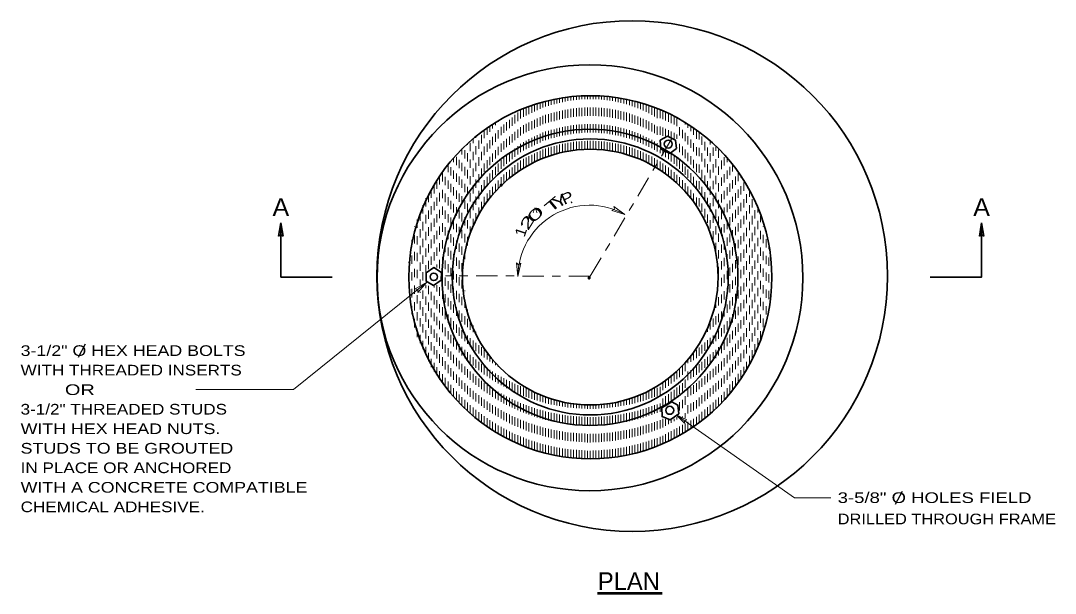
# Model space of a CAD drawing. Extents: x 21 to 35.7, y -17 to 3.5.
# Drawn here: x 20.95 to 33.31, y -3.3 to 3.53 of the extents above; entities that cross this region are included whole.
import ezdxf
from ezdxf.enums import TextEntityAlignment as Align

# ---------------------------------------------------------------- set-up
doc = ezdxf.new("R2010")
doc.units = 0
doc.header["$LTSCALE"] = 0.051
doc.header["$PDMODE"] = 32
doc.header["$PDSIZE"] = 0.0255
doc.linetypes.add('DOT_DASHED', pattern=[7.7, 5, -1.2, 0.3, -1.2])
doc.linetypes.add('DOTTED', pattern=[1.5, 0.3, -1.2])
for name, color, linetype, lineweight in [('1', 7, 'Continuous', 35), ('10', 7, 'Continuous', 13), ('12', 7, 'Continuous', 53), ('6', 7, 'DOTTED', 13)]:
    doc.layers.add(name, color=color, linetype=linetype, lineweight=lineweight)
doc.layers.add('13', color=7, linetype='Continuous')

msp = doc.modelspace()

# ---------------------------------------------------------------- linework, layer by layer
at = {"layer": '1'}
for points in [[(28.59758, 2.00233), (28.59133, 2.10583), (28.679, 2.15458), (28.77467, 2.10658), (28.78675, 2.008), (28.7065, 1.9495), (28.596, 2.00225)], [(25.79592, 0.52508), (25.79583, 0.42283), (25.88133, 0.37258), (25.97375, 0.43442), (25.97908, 0.52733), (25.88733, 0.58542), (25.79433, 0.52508)], [(28.60458, -1.09383), (28.73133, -1.01733), (28.80033, -1.05492), (28.81558, -1.15842)], [(28.81558, -1.15842), (28.70908, -1.2305), (28.61467, -1.19242), (28.61258, -1.08567)]]:
    msp.add_lwpolyline(points, dxfattribs=at)
for centre, radius in [((28.25679, 0.48523), 3.04856), ((27.75217, 0.46448), 2.54294), ((27.75712, 0.47011), 2.16788), ((27.75254, 0.46952), 1.76838), ((27.75604, 0.47411), 1.64783), ((28.68796, 2.06094), 0.04811), ((27.75608, 0.47207), 1.5266), ((25.88642, 0.47561), 0.04411), ((28.70554, -1.11781), 0.04834)]:
    msp.add_circle(centre, radius, dxfattribs=at)
at = {"layer": '10', "linetype": 'DOT_DASHED'}
for q in [(28.77775, 2.2065), (26.02467, 0.48733)]:
    msp.add_line((27.75683, 0.48358), q, dxfattribs=at)
at = {"layer": '10'}
for p, q in [((28.01425, 1.26942), (28.04417, 1.28408)), ((28.01425, 1.26942), (28.04417, 1.28408)), ((28.01425, 1.26942), (28.169, 1.22075)), ((28.01425, 1.26942), (28.169, 1.22075)), ((28.03842, 1.31692), (28.169, 1.22075)), ((28.03842, 1.31692), (28.04417, 1.28408)), ((28.03842, 1.31692), (28.169, 1.22075)), ((28.03842, 1.31692), (28.04417, 1.28408)), ((26.87433, 0.64133), (26.89142, 0.48)), ((26.87433, 0.64133), (26.89975, 0.61975)), ((26.92758, 0.63817), (26.89142, 0.48)), ((26.92758, 0.63817), (26.89975, 0.61975)), ((25.66283, 0.33058), (25.80425, 0.41)), ((25.69625, 0.289), (25.80425, 0.41)), ((25.66283, 0.33058), (25.69508, 0.32233)), ((25.69625, 0.289), (25.69508, 0.32233)), ((28.88308, -1.27175), (28.78167, -1.17242)), ((28.90983, -1.2335), (28.78167, -1.17242)), ((28.90983, -1.2335), (28.88208, -1.24258)), ((28.88308, -1.27175), (28.88208, -1.24258))]:
    msp.add_line(p, q, dxfattribs=at)
at = {"layer": '10', "lineweight": 35}
for p, q in [((24.03292, 0.95942), (24.05967, 1.11942)), ((24.08625, 0.95942), (24.05967, 1.11942)), ((32.40442, 0.95942), (32.431, 1.11942)), ((32.45775, 0.95942), (32.431, 1.11942)), ((24.03292, 0.95942), (24.05958, 0.97942)), ((24.08625, 0.95942), (24.05958, 0.97942)), ((32.40442, 0.95942), (32.43108, 0.97942)), ((32.45775, 0.95942), (32.43108, 0.97942))]:
    msp.add_line(p, q, dxfattribs=at)
for points in [[(24.67267, 0.47292), (24.05967, 0.47292), (24.05967, 1.11942)], [(31.818, 0.47292), (32.431, 0.47292), (32.431, 1.11942)]]:
    msp.add_lwpolyline(points, dxfattribs=at)
at = {"layer": '10'}
for points in [[(23.04342, -0.87133), (24.21242, -0.86925), (25.80425, 0.41)], [(30.62833, -2.16142), (30.19742, -2.16142), (28.78167, -1.17242)]]:
    msp.add_lwpolyline(points, dxfattribs=at)
msp.add_arc((27.74844, 0.47402), 0.85704, 60.61232, 179.59848, dxfattribs=at)
at = {"layer": '12', "lineweight": 25}
for p, q in [((21.64067, -0.48267), (21.72408, -0.32617)), ((31.40242, -2.23967), (31.48583, -2.08317))]:
    msp.add_line(p, q, dxfattribs=at)
at = {"layer": '12'}
msp.add_line((27.84192, -3.30308), (28.61558, -3.30308), dxfattribs=at)
at = {"layer": '6'}
for p, q in [((27.3565, 1.94542), (27.3565, 2.60058)), ((27.38983, 1.95408), (27.38983, 2.60658)), ((27.42317, 1.96192), (27.42317, 2.61208)), ((27.4565, 1.96892), (27.4565, 2.617)), ((27.48983, 1.97525), (27.48983, 2.62142)), ((27.52317, 1.98075), (27.52317, 2.62533)), ((27.5565, 1.9855), (27.5565, 2.62867)), ((27.58983, 1.98958), (27.58983, 2.6315)), ((27.62317, 1.99283), (27.62317, 2.63383)), ((27.6565, 1.99542), (27.6565, 2.63558)), ((27.68983, 1.99717), (27.68983, 2.63692)), ((27.72317, 1.99825), (27.72317, 2.63767)), ((27.7565, 1.99867), (27.7565, 2.638)), ((27.78992, 1.99825), (27.78992, 2.63775)), ((27.82317, 1.99717), (27.82317, 2.63692)), ((27.8565, 1.99533), (27.8565, 2.63567)), ((27.88983, 1.99275), (27.88983, 2.63392)), ((27.92317, 1.9895), (27.92317, 2.63158)), ((27.9565, 1.98542), (27.9565, 2.62875)), ((27.98983, 1.98067), (27.98983, 2.62542)), ((28.02317, 1.97508), (28.02317, 2.62158)), ((28.0565, 1.96875), (28.0565, 2.61717)), ((28.08983, 1.96175), (28.08983, 2.61225)), ((28.12317, 1.95383), (28.12317, 2.60683)), ((28.1565, 1.94517), (28.1565, 2.60083)), ((26.9565, 1.78517), (26.9565, 2.48467)), ((26.98983, 1.80125), (26.98983, 2.49767)), ((27.02317, 1.81733), (27.02317, 2.50992)), ((27.0565, 1.83325), (27.0565, 2.52158)), ((27.08983, 1.84942), (27.08983, 2.53267)), ((27.12317, 1.86542), (27.12317, 2.54317)), ((27.15658, 1.8815), (27.15658, 2.55308)), ((27.18983, 1.89758), (27.18983, 2.56242)), ((27.22317, 1.90892), (27.22317, 2.57117)), ((27.2565, 1.91925), (27.2565, 2.57933)), ((27.28983, 1.92967), (27.28983, 2.587)), ((27.32317, 1.936), (27.32317, 2.59408)), ((28.18983, 1.93575), (28.18983, 2.59433)), ((28.22317, 1.92542), (28.22317, 2.58725)), ((28.2565, 1.91425), (28.2565, 2.57967)), ((28.28983, 1.90225), (28.28983, 2.5715)), ((28.32325, 1.88933), (28.32325, 2.56275)), ((28.3565, 1.87558), (28.3565, 2.55342)), ((28.38983, 1.86092), (28.38983, 2.54358)), ((28.42317, 1.84517), (28.42317, 2.53308)), ((28.4565, 1.8285), (28.4565, 2.52208)), ((28.48983, 1.81075), (28.48983, 2.51042)), ((28.52317, 1.79192), (28.52317, 2.49808)), ((28.5565, 1.772), (28.5565, 2.48517)), ((26.68983, 1.56667), (26.68983, 2.357)), ((26.72317, 1.59567), (26.72317, 2.3755)), ((26.7565, 1.62367), (26.7565, 2.39325)), ((26.78983, 1.65183), (26.78983, 2.41017)), ((26.82317, 1.67992), (26.82317, 2.4265)), ((26.8565, 1.708), (26.8565, 2.442)), ((26.88983, 1.73608), (26.88983, 2.45692)), ((26.92317, 1.76425), (26.92317, 2.47117)), ((28.58983, 2.47167), (28.58983, 2.1295)), ((28.62317, 2.4575), (28.62317, 2.13242)), ((28.6565, 2.44258), (28.6565, 2.15383)), ((28.68983, 2.42708), (28.68983, 2.15817)), ((28.72317, 2.41083), (28.72317, 2.14192)), ((28.7565, 2.39383), (28.7565, 2.12667)), ((28.78983, 2.37617), (28.78983, 2.12233)), ((28.82317, 1.56375), (28.82317, 2.35775)), ((26.52317, 1.36933), (26.52317, 2.2425)), ((26.5565, 1.40883), (26.5565, 2.27517)), ((26.58983, 1.44833), (26.58983, 2.29683)), ((26.62325, 1.48783), (26.62325, 2.31775)), ((26.6565, 1.52725), (26.6565, 2.33775)), ((28.8565, 1.53017), (28.8565, 2.3385)), ((28.88983, 1.49433), (28.88983, 2.3185)), ((28.92317, 1.45608), (28.92317, 2.29767)), ((28.9565, 1.41517), (28.9565, 2.271)), ((28.98983, 1.37117), (28.98983, 2.248)), ((29.02317, 1.3235), (29.02317, 2.22983)), ((26.3565, 1.06975), (26.3565, 2.11792)), ((26.38983, 1.13625), (26.38983, 2.146)), ((26.42317, 1.20267), (26.42317, 2.174)), ((26.4565, 1.26925), (26.4565, 2.20058)), ((26.48983, 1.32992), (26.48983, 2.22158)), ((29.0565, 1.31683), (29.0565, 2.20542)), ((29.08983, 1.25125), (29.08983, 2.17992)), ((29.12317, 1.1855), (29.12317, 2.15342)), ((29.1565, 1.11975), (29.1565, 2.12583)), ((26.22317, -1.06183), (26.22317, 2.00592)), ((26.2565, 0.68717), (26.2565, 2.034)), ((26.28983, 0.85133), (26.28983, 2.062)), ((26.32317, 0.977), (26.32317, 2.08992)), ((28.58983, 1.75083), (28.58983, 1.99392)), ((28.62317, 1.7285), (28.62317, 1.98058)), ((29.18983, 1.05408), (29.18983, 2.09708)), ((29.22317, 0.92042), (29.22317, 2.06708)), ((29.2565, 0.78017), (29.2565, 2.03583)), ((29.28983, 0.49492), (29.28983, 2.00325)), ((26.12317, -0.95467), (26.12317, 1.89258)), ((26.1565, -0.992), (26.1565, 1.93233)), ((26.18983, -1.02767), (26.18983, 1.97192)), ((28.6565, 1.70483), (28.6565, 1.96333)), ((28.68983, 1.67975), (28.68983, 1.94717)), ((28.72317, 1.65325), (28.72317, 1.93758)), ((28.7565, 1.62517), (28.7565, 1.971)), ((28.78983, 1.59533), (28.78983, 1.96625)), ((29.32317, -1.03692), (29.32317, 1.96917)), ((29.3565, -0.997), (29.3565, 1.9335)), ((29.38983, -0.95425), (29.38983, 1.89625)), ((29.42317, -0.91133), (29.42317, 1.85717)), ((26.02317, -0.83108), (26.02317, 1.77367)), ((26.0565, -0.87442), (26.0565, 1.81333)), ((26.08983, -0.9155), (26.08983, 1.85308)), ((29.4565, -0.86858), (29.4565, 1.81608)), ((29.48983, -0.82583), (29.48983, 1.77292)), ((25.92317, 1.62442), (25.92317, 0.58675)), ((25.9565, 1.67692), (25.9565, 0.55383)), ((25.98983, -0.78542), (25.98983, 1.72933)), ((29.52317, -0.78292), (29.52317, 1.72742)), ((29.5565, -0.74017), (29.5565, 1.67917)), ((29.58983, -0.69733), (29.58983, 1.62808)), ((25.8565, 1.51933), (25.8565, 0.57767)), ((25.88983, 1.57183), (25.88983, 0.59675)), ((29.62317, -0.63933), (29.62317, 1.5735)), ((29.6565, -0.56867), (29.6565, 1.51508)), ((25.78983, 1.41417), (25.78983, 0.41958)), ((25.82317, 1.46675), (25.82317, 0.55667)), ((29.68983, -0.49808), (29.68983, 1.45208)), ((25.72317, 1.24558), (25.72317, 0.37758)), ((25.7565, 1.33058), (25.7565, 0.39575)), ((29.72317, -0.4275), (29.72317, 1.35267)), ((29.7565, -0.35683), (29.7565, 1.28583)), ((25.68983, 1.16067), (25.68983, 0.36417)), ((29.78983, -0.27358), (29.78983, 1.19825)), ((25.6565, -0.12775), (25.6565, 1.076)), ((29.82317, -0.12383), (29.82317, 1.081)), ((25.62317, 0.03075), (25.62317, 0.91592)), ((29.8565, 0.026), (29.8565, 0.96367)), ((29.88983, 0.20692), (29.88983, 0.83675)), ((25.58983, 0.44217), (25.58983, 0.64925)), ((25.78983, -0.46025), (25.78983, 0.37617)), ((25.82317, -0.53225), (25.82317, 0.391)), ((25.8565, -0.60425), (25.8565, 0.37333)), ((25.92317, -0.70142), (25.92317, 0.37717)), ((25.9565, -0.74975), (25.9565, 0.39958)), ((25.68983, -0.2445), (25.68983, 0.28017)), ((25.72317, -0.31642), (25.72317, 0.29642)), ((25.7565, -0.38842), (25.7565, 0.35183)), ((25.88983, -0.65317), (25.88983, 0.36567)), ((26.2565, -1.0945), (26.2565, 0.31075)), ((29.28983, -1.06567), (29.28983, 0.27367)), ((29.2565, -1.09442), (29.2565, 0.1455)), ((26.28983, -1.12575), (26.28983, 0.08575)), ((29.22317, -1.12317), (29.22317, 0.01708)), ((26.32317, -1.15575), (26.32317, -0.03333)), ((26.3565, -1.18458), (26.3565, -0.1065)), ((29.18983, -1.15192), (29.18983, -0.06408)), ((26.38983, -1.21225), (26.38983, -0.17958)), ((29.12317, -1.20942), (29.12317, -0.2035)), ((29.1565, -1.18067), (29.1565, -0.13375)), ((26.42317, -1.23875), (26.42317, -0.25258)), ((26.4565, -1.26433), (26.4565, -0.309)), ((26.48983, -1.28883), (26.48983, -0.35117)), ((29.0565, -1.26692), (29.0565, -0.34275)), ((29.08983, -1.23825), (29.08983, -0.27317)), ((26.52317, -1.31233), (26.52317, -0.42817)), ((26.5565, -1.335), (26.5565, -0.47217)), ((28.9565, -1.338), (28.9565, -0.468)), ((28.98983, -1.31958), (28.98983, -0.42625)), ((29.02317, -1.29567), (29.02317, -0.38467)), ((26.58983, -1.35667), (26.58983, -0.513)), ((26.62325, -1.37758), (26.62325, -0.55125)), ((26.6565, -1.39758), (26.6565, -0.58692)), ((28.8565, -0.59283), (28.8565, -1.19825)), ((28.88983, -0.55117), (28.88983, -1.21217)), ((28.92317, -1.35633), (28.92317, -0.5095)), ((26.68983, -1.41683), (26.68983, -0.6205)), ((26.72317, -1.43533), (26.72317, -0.65208)), ((26.7565, -1.45308), (26.7565, -0.68183)), ((26.78983, -1.47), (26.78983, -0.70983)), ((26.82317, -1.48633), (26.82317, -0.73633)), ((28.68983, -0.72458), (28.68983, -1.035)), ((28.72317, -0.69892), (28.72317, -1.0145)), ((28.7565, -0.67317), (28.7565, -1.02025)), ((28.78983, -0.6475), (28.78983, -1.02642)), ((28.82317, -0.62183), (28.82317, -1.18058)), ((26.8565, -1.50183), (26.8565, -0.76133)), ((26.88983, -1.51675), (26.88983, -0.785)), ((26.92317, -1.531), (26.92317, -0.80733)), ((26.9565, -1.5445), (26.9565, -0.82842)), ((26.98983, -1.5575), (26.98983, -0.84833)), ((28.52317, -1.55792), (28.52317, -0.84783)), ((28.5565, -1.54917), (28.5565, -0.82742)), ((28.58983, -1.53667), (28.58983, -0.80175)), ((28.62317, -0.77592), (28.62317, -1.07033)), ((28.6565, -0.75033), (28.6565, -1.05408)), ((27.02317, -1.56975), (27.02317, -0.86708)), ((27.0565, -1.58142), (27.0565, -0.88483)), ((27.08983, -1.5925), (27.08983, -0.9015)), ((27.12317, -1.603), (27.12317, -0.91717)), ((27.1565, -1.61292), (27.1565, -0.93192)), ((27.18983, -1.62225), (27.18983, -0.94567)), ((27.22317, -1.631), (27.22317, -0.9585)), ((27.2565, -1.63917), (27.2565, -0.9705)), ((27.28983, -1.64683), (27.28983, -0.98158)), ((28.22317, -1.64708), (28.22317, -0.98133)), ((28.2565, -1.6395), (28.2565, -0.97017)), ((28.28983, -1.63133), (28.28983, -0.95817)), ((28.32317, -1.62258), (28.32317, -0.94533)), ((28.3565, -1.61325), (28.3565, -0.9315)), ((28.38983, -1.60342), (28.38983, -0.91683)), ((28.42317, -1.59292), (28.42317, -0.90108)), ((28.4565, -1.58192), (28.4565, -0.88442)), ((28.48983, -1.57025), (28.48983, -0.86667)), ((27.32317, -1.65392), (27.32317, -0.99192)), ((27.3565, -1.661), (27.3565, -1.00133)), ((27.38983, -1.66658), (27.38983, -1.01)), ((27.42317, -1.67225), (27.42317, -1.01783)), ((27.4565, -1.67792), (27.4565, -1.02483)), ((27.48983, -1.6835), (27.48983, -1.03117)), ((27.52317, -1.68517), (27.52317, -1.03667)), ((27.5565, -1.6885), (27.5565, -1.04142)), ((27.58983, -1.69133), (27.58983, -1.0455)), ((27.62317, -1.69367), (27.62317, -1.04875)), ((27.6565, -1.69542), (27.6565, -1.05133)), ((27.68983, -1.69675), (27.68983, -1.05308)), ((27.72317, -1.702), (27.72317, -1.05417)), ((27.7565, -1.70092), (27.7565, -1.05458)), ((27.78983, -1.69992), (27.78992, -1.05417)), ((27.82317, -1.69892), (27.82317, -1.05308)), ((27.8565, -1.69792), (27.8565, -1.05125)), ((27.88983, -1.69375), (27.88983, -1.04867)), ((27.92317, -1.69142), (27.92317, -1.04542)), ((27.9565, -1.68858), (27.9565, -1.04133)), ((27.98983, -1.68525), (27.98983, -1.03658)), ((28.02317, -1.68142), (28.02317, -1.031)), ((28.0565, -1.677), (28.0565, -1.02467)), ((28.08983, -1.67208), (28.08983, -1.01767)), ((28.12317, -1.66667), (28.12317, -1.00975)), ((28.1565, -1.66067), (28.1565, -1.00108)), ((28.18983, -1.65417), (28.18983, -0.99167)), ((28.62317, -1.5215), (28.62317, -1.20833)), ((28.6565, -1.50317), (28.6565, -1.22267)), ((28.68983, -1.48475), (28.68983, -1.23075)), ((28.72317, -1.46633), (28.72317, -1.23317)), ((28.7565, -1.44808), (28.7565, -1.21883)), ((28.78983, -1.42975), (28.78983, -1.19825)), ((28.82317, -1.41142), (28.82317, -1.23167)), ((28.8565, -1.39308), (28.8565, -1.25458)), ((28.88983, -1.37467), (28.88983, -1.27367))]:
    msp.add_line(p, q, dxfattribs=at)
for p in [(26.69283, 1.57008), (27.7425, 0.46208)]:
    msp.add_point(p, dxfattribs=at)

# ---------------------------------------------------------------- texts
at = {"layer": '12', "width": 1.05}
for p in [(24.05971, 1.20267), (32.43104, 1.20267)]:
    msp.add_text('A', height=0.212, dxfattribs=at).set_placement(p, align=Align.CENTER)
at = {"layer": '12'}
for s, width, p in [('3-1/2" O HEX HEAD BOLTS', 1.25, (20.95075, -0.46917)), ('WITH THREADED INSERTS', 1.2, (20.95075, -0.70233)), ('        OR', 1.4, (20.95075, -0.9355)), ('3-1/2" THREADED STUDS', 1.2, (20.95075, -1.16867)), ('WITH HEX HEAD NUTS.', 1.25, (20.95075, -1.40183)), ('STUDS TO BE GROUTED ', 1.25, (20.95075, -1.635)), ('IN PLACE OR ANCHORED', 1.2, (20.95075, -1.86817)), ('WITH A CONCRETE COMPATIBLE ', 1.25, (20.95075, -2.10133)), ('3-5/8" O HOLES FIELD', 1.3, (30.71167, -2.225)), ('CHEMICAL ADHESIVE.', 1.2, (20.95075, -2.3345)), ('DRILLED THROUGH FRAME', 1.15, (30.71167, -2.47933))]:
    msp.add_text(s, height=0.1272, dxfattribs=dict(at, width=width)).set_placement(p)
msp.add_text('PLAN', height=0.212, dxfattribs=at).set_placement((28.21717, -3.26367), align=Align.CENTER)
at = {"layer": '13'}
for s, rotation, width, p in [('P', 24.703, 1.25, (27.44383, 1.33217)), ('T', 39.869, 1.85, (27.27533, 1.22633)), ('Y', 32.018, 1.45, (27.35825, 1.28258)), ('0', 41.768, 2.1, (27.067, 1.10658)), ('2', 58.716, 1.8, (27.012, 1.01933)), ('1', 71.651, 1.1, (26.96992, 0.94325))]:
    msp.add_text(s, height=0.1272, rotation=rotation, dxfattribs=dict(at, width=width)).set_placement(p)
msp.add_text('.', height=0.1272, rotation=18.573, dxfattribs=at).set_placement((27.5135, 1.34783))
at = {"layer": '13', "width": 0.75}
msp.add_text('^ ', height=0.1272, dxfattribs=at).set_placement((27.067, 1.17508))

doc.saveas('drawing.dxf')
